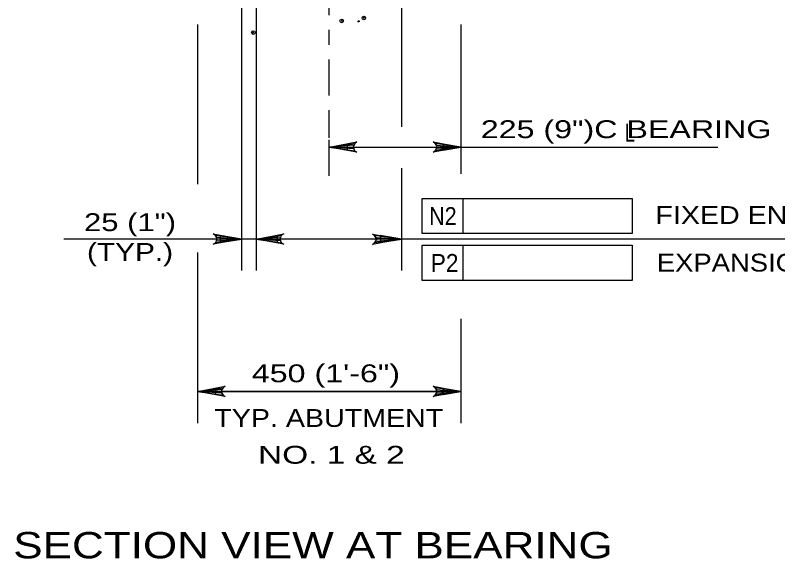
# Model space of a CAD drawing. Extents: x -11 to 79, y -154 to 0.
# Drawn here: x 40.96 to 46.09, y -54.41 to -50.76 of the extents above; entities that cross this region are included whole.
import ezdxf
from ezdxf.enums import TextEntityAlignment as Align

# ---------------------------------------------------------------- set-up
doc = ezdxf.new("R2010")
doc.units = 0
doc.header["$LTSCALE"] = 0.048
doc.header["$PDMODE"] = 32
doc.header["$PDSIZE"] = 0.024
doc.linetypes.add('DOT_DASHED', pattern=[7.7, 5, -1.2, 0.3, -1.2])
for name, color, linetype, lineweight in [('3', 7, 'Continuous', 25), ('4', 7, 'Continuous', 25), ('5', 7, 'Continuous', 25)]:
    doc.layers.add(name, color=color, linetype=linetype, lineweight=lineweight)

msp = doc.modelspace()

# ---------------------------------------------------------------- hatches: boundary and pattern name
at = {"layer": '3'}
for points in [[(43.19333, -51.622), (43.19333, -51.662), (43.07333, -51.642)], [(43.83925, -51.622), (43.83925, -51.662), (43.95925, -51.642)], [(42.34083, -52.23608), (42.34083, -52.28333), (42.48258, -52.25967)], [(42.72275, -52.23608), (42.72275, -52.28333), (42.581, -52.25967)], [(43.41783, -52.23608), (43.41783, -52.28333), (43.55958, -52.25967)], [(42.3075, -53.26433), (42.3075, -53.30433), (42.1875, -53.28433)], [(43.83925, -53.26433), (43.83925, -53.30433), (43.95925, -53.28433)]]:
    msp.add_hatch(color=256, dxfattribs=at).paths.add_polyline_path(points)

# ---------------------------------------------------------------- linework, layer by layer
for p, q in [((42.48258, -49.12425), (42.48258, -52.47233)), ((42.581, -49.33283), (42.581, -52.47233)), ((43.55958, -49.33283), (43.55958, -51.50558)), ((42.1875, -50.81875), (42.1875, -51.89067)), ((43.95925, -50.81875), (43.95925, -51.77583)), ((43.07333, -51.5795), (43.07333, -51.462)), ((43.07333, -51.642), (44.24267, -51.642)), ((43.19333, -51.642), (43.83925, -51.642)), ((44.24267, -51.642), (45.68775, -51.642)), ((43.95925, -51.7045), (43.95925, -51.822)), ((43.55958, -51.78258), (43.55958, -52.47233)), ((43.69867, -51.98625), (45.11058, -51.98625)), ((43.69867, -52.2225), (43.69867, -51.98625)), ((43.97425, -52.2225), (43.97425, -51.98625)), ((45.11058, -51.98625), (45.11058, -52.2225)), ((46.5995, -52.25967), (41.28892, -52.25967)), ((45.11058, -52.2225), (43.69867, -52.2225)), ((43.69867, -52.30158), (45.11058, -52.30158)), ((43.69867, -52.53783), (43.69867, -52.30158)), ((43.97425, -52.53783), (43.97425, -52.30158)), ((45.11058, -52.30158), (45.11058, -52.53783)), ((42.1875, -52.34942), (42.1875, -53.497)), ((45.11058, -52.53783), (43.69867, -52.53783)), ((43.95925, -52.79617), (43.95925, -53.497)), ((42.1875, -53.03308), (42.1875, -53.46433)), ((43.95925, -53.20875), (43.95925, -53.46433)), ((43.95925, -53.28433), (42.1875, -53.28433)), ((42.3075, -53.28433), (43.83925, -53.28433))]:
    msp.add_line(p, q, dxfattribs=at)
for points in [[(43.07333, -51.642), (43.25975, -51.60708), (43.24542, -51.617), (43.238, -51.6295), (43.23583, -51.642), (43.238, -51.6545), (43.24542, -51.667), (43.25975, -51.67692), (43.07333, -51.642), (43.24542, -51.667), (43.238, -51.6545), (43.07333, -51.642), (43.23583, -51.642), (43.238, -51.6295), (43.07333, -51.642), (43.24542, -51.617)], [(43.95925, -51.642), (43.77283, -51.67692), (43.78717, -51.667), (43.79458, -51.6545), (43.79675, -51.642), (43.79458, -51.6295), (43.78717, -51.617), (43.77283, -51.60708), (43.95925, -51.642), (43.78717, -51.617), (43.79458, -51.6295), (43.95925, -51.642), (43.79675, -51.642), (43.79458, -51.6545), (43.95925, -51.642), (43.78717, -51.667)], [(42.47992, -52.26008), (42.2935, -52.29508), (42.30783, -52.28508), (42.31525, -52.27258), (42.31742, -52.26008), (42.31525, -52.24758), (42.30783, -52.23508), (42.2935, -52.22517), (42.47992, -52.26008), (42.30783, -52.23508), (42.31525, -52.24758), (42.47992, -52.26008), (42.31742, -52.26008), (42.31525, -52.27258), (42.47992, -52.26008), (42.30783, -52.28508)], [(42.581, -52.25967), (42.76742, -52.22475), (42.75308, -52.23467), (42.74567, -52.24717), (42.7435, -52.25967), (42.74567, -52.27217), (42.75308, -52.28467), (42.76742, -52.29458), (42.581, -52.25967), (42.75308, -52.28467), (42.74567, -52.27217), (42.581, -52.25967), (42.7435, -52.25967), (42.74567, -52.24717), (42.581, -52.25967), (42.75308, -52.23467)], [(43.55117, -52.26108), (43.36475, -52.296), (43.37908, -52.28608), (43.3865, -52.27358), (43.38867, -52.26108), (43.3865, -52.24858), (43.37908, -52.23608), (43.36475, -52.22608), (43.55117, -52.26108), (43.37908, -52.23608), (43.3865, -52.24858), (43.55117, -52.26108), (43.38867, -52.26108), (43.3865, -52.27358), (43.55117, -52.26108), (43.37908, -52.28608)]]:
    msp.add_lwpolyline(points, dxfattribs=at)
for points in [[(43.19333, -51.622), (43.19333, -51.662), (43.07333, -51.642)], [(43.83925, -51.622), (43.83925, -51.662), (43.95925, -51.642)], [(42.34083, -52.23608), (42.34083, -52.28333), (42.48258, -52.25967)], [(42.72275, -52.23608), (42.72275, -52.28333), (42.581, -52.25967)], [(43.41783, -52.23608), (43.41783, -52.28333), (43.55958, -52.25967)], [(42.3075, -53.26433), (42.3075, -53.30433), (42.1875, -53.28433)], [(43.83925, -53.26433), (43.83925, -53.30433), (43.95925, -53.28433)]]:
    msp.add_lwpolyline(points, close=True, dxfattribs=at)
at = {"layer": '4'}
for p, q in [((43.2655, -50.80192), (43.27508, -50.79042)), ((43.277, -50.80067), (43.27517, -50.79042))]:
    msp.add_line(p, q, dxfattribs=at)
for points in [[(42.1875, -53.28433), (42.37392, -53.24942), (42.35958, -53.25933), (42.35217, -53.27183), (42.35, -53.28433), (42.35217, -53.29683), (42.35958, -53.30933), (42.37392, -53.31925), (42.1875, -53.28433), (42.35958, -53.30933), (42.35217, -53.29683), (42.1875, -53.28433), (42.35, -53.28433), (42.35217, -53.27183), (42.1875, -53.28433), (42.35958, -53.25933)], [(43.95925, -53.28433), (43.77283, -53.31925), (43.78717, -53.30933), (43.79458, -53.29683), (43.79675, -53.28433), (43.79458, -53.27183), (43.78717, -53.25933), (43.77283, -53.24942), (43.95925, -53.28433), (43.78717, -53.25933), (43.79458, -53.27183), (43.95925, -53.28433), (43.79675, -53.28433), (43.79458, -53.29683), (43.95925, -53.28433), (43.78717, -53.30933)]]:
    msp.add_lwpolyline(points, dxfattribs=at)
for p in [(43.30667, -50.77392), (43.1575, -50.79358), (42.56267, -50.87183)]:
    msp.add_point(p, dxfattribs=at)
at = {"layer": '5', "linetype": 'DOT_DASHED'}
msp.add_line((43.07333, -51.83392), (43.07333, -46.7625), dxfattribs=at)

# ---------------------------------------------------------------- texts
at = {"layer": '3'}
for s, height, width, p in [('225 (9")C BEARING', 0.12, 1.35, (45.07033, -51.5815)), ('N2', 0.12, 0.9, (43.83821, -52.16533)), ('FIXED END', 0.12, 1.2, (45.78104, -52.1585)), ('25 (1")', 0.12, 1.3, (41.73354, -52.20658)), ('(TYP.)', 0.12, 1.25, (41.73358, -52.40658)), ('P2', 0.12, 0.95, (43.84971, -52.48058)), ('EXPANSION END', 0.12, 1.15, (46.03583, -52.47842)), ('450 (1\'-6")', 0.12, 1.35, (43.05112, -53.2225)), ('TYP. ABUTMENT', 0.12, 1.2, (43.07062, -53.52275)), ('NO. 1 & 2', 0.12, 1.4, (43.08808, -53.77)), ('SECTION VIEW AT BEARING', 0.1772, 1.25, (42.96412, -54.40633))]:
    msp.add_text(s, height=height, dxfattribs=dict(at, width=width)).set_placement(p, align=Align.CENTER)
at = {"layer": '3', "width": 0.75}
msp.add_text('L', height=0.12, dxfattribs=at).set_placement((45.06308, -51.60517))

doc.saveas('drawing.dxf')
